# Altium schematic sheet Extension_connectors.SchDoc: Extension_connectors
size A4; Date: Not used; ApprovedBy: Not used; CheckedBy: Not used; Author: Not used; CompanyName: STMicroelectronics; DrawnBy: Not used; Engineer: Not used; Organization: Not used; Address1: Not used; Address2: Not used; Address3: Not used; Address4: Not used; DocumentNumber: Not used; Revision: Not used; SheetNumber: 8; SheetTotal: 12
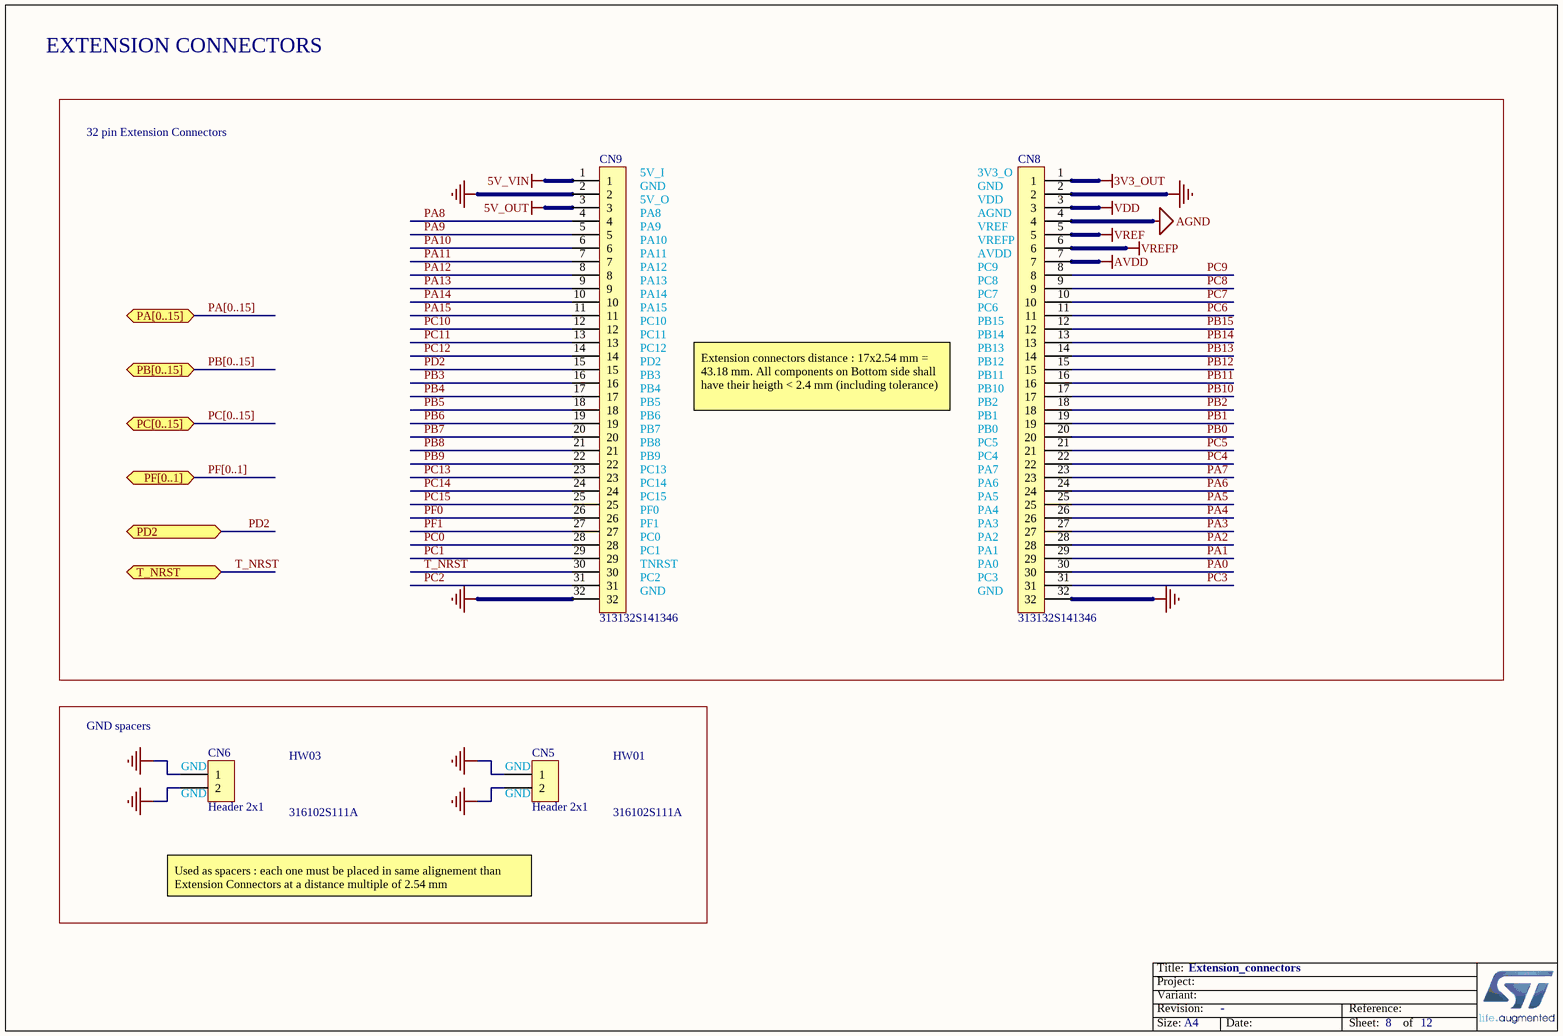
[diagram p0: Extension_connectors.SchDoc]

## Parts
CN5  Header 2x1  [CON_LYCONN_313102S141346]
CN6  Header 2x1  [CON_LYCONN_313102S141346]
CN8  value 313132S141346  [CON_LYCONN_313132S141346]  (hidden comment: Header 32x1)
CN9  value 313132S141346  [CON_LYCONN_313132S141346]  (hidden comment: Header 32x1)
HW01  value 316102S111A  (hidden comment: JUMPER_OPEN)
HW03  value 316102S111A  (hidden comment: JUMPER_OPEN)

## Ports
PA[0..15] (bidir), PB[0..15] (bidir), PC[0..15] (bidir), PD2, PF[0..1] (bidir), T_NRST

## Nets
3V3_OUT: CN8.1
5V_OUT: CN9.3
5V_VIN: CN9.1
AGND: CN8.4
AVDD: CN8.7
GND: CN5.1 CN5.2 CN6.1 CN6.2 CN8.2 CN8.32 CN9.2 CN9.32
VDD: CN8.3
VREF: CN8.5
VREFP: CN8.6
PA0: CN8.30
PA1: CN8.29
PA2: CN8.28
PA3: CN8.27
PA4: CN8.26
PA5: CN8.25
PA6: CN8.24
PA7: CN8.23
PA8: CN9.4
PA9: CN9.5
PA10: CN9.6
PA11: CN9.7
PA12: CN9.8
PA13: CN9.9
PA14: CN9.10
PA15: CN9.11
PB0: CN8.20
PB1: CN8.19
PB2: CN8.18
PB3: CN9.16
PB4: CN9.17
PB5: CN9.18
PB6: CN9.19
PB7: CN9.20
PB8: CN9.21
PB9: CN9.22
PB10: CN8.17
PB11: CN8.16
PB12: CN8.15
PB13: CN8.14
PB14: CN8.13
PB15: CN8.12
PC0: CN9.28
PC1: CN9.29
PC2: CN9.31
PC3: CN8.31
PC4: CN8.22
PC5: CN8.21
PC6: CN8.11
PC7: CN8.10
PC8: CN8.9
PC9: CN8.8
PC10: CN9.12
PC11: CN9.13
PC12: CN9.14
PC13: CN9.23
PC14: CN9.24
PC15: CN9.25
PD2: CN9.15 ; port PD2
PF0: CN9.26
PF1: CN9.27
T_NRST: CN9.30 ; port T_NRST

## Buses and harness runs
bus PA[0..15] = port PA[0..15]
bus PB[0..15] = port PB[0..15]
bus PC[0..15] = port PC[0..15]
bus PF[0..1] = port PF[0..1]

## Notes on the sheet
- EXTENSION CONNECTORS
- 32 pin Extension Connectors
- (near CN9) 5V_I
- (near CN8) 3V3_O
- (near CN9) GND
- (near CN9) 5V_O
- (near CN9) PA8
- (near CN9) PA10
- (near CN9) PA9
- (near CN8) GND
- (near CN8) VDD
- (near CN8) VREF
- (near CN8) AGND
- (near CN8) VREFP
- (near CN9) PA15
- (near CN9) PA14
- (near CN9) PA13
- (near CN9) PA12
- (near CN9) PA11
- (near CN8) AVDD
- (near CN8) PC6
- (near CN8) PC7
- (near CN8) PC8
- (near CN8) PC9
- (near CN9) PB3
- (near CN9) PD2
- (near CN9) PC12
- (near CN9) PC11
- (near CN9) PC10
- (near CN8) PB11
- (near CN8) PB12
- (near CN8) PB13
- (near CN8) PB14
- (near CN8) PB15
- (near CN9) PB7
- (near CN9) PB8
- (near CN9) PB6
- (near CN9) PB5
- (near CN9) PB4
- Extension connectors distance : 17x2.54 mm = 43.18 mm. All components on Bottom side shall have their heigth < 2.4 mm (including tolerance)
- (near CN8) PC5
- (near CN8) PB0
- (near CN8) PB1
- (near CN8) PB2
- (near CN8) PB10
- (near CN9) PF0
- (near CN9) PC15
- (near CN9) PC14
- (near CN9) PC13
- (near CN9) PB9
- (near CN8) PA4
- (near CN8) PA5
- (near CN8) PA6
- (near CN8) PA7
- (near CN8) PC4
- (near CN9) TNRST
- (near CN9) PC2
- (near CN9) PC1
- (near CN9) PC0
- (near CN9) PF1
- (near CN8) PC3
- (near CN8) PA0
- (near CN8) PA1
- (near CN8) PA2
- (near CN8) PA3
- GND spacers
- (near CN6) GND
- (near CN5) GND
- Used as spacers : each one must be placed in same alignement than Extension Connectors at a distance multiple of 2.54 mm

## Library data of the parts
CN5 CN6 = MCD-01668: Header 2x1, 2.54mm, VR, TH, height 5.84mm/5.08 mm, height total 13.46 mm; Part_Type: Connector; Manufacturer_Part_Number: 313102S141346; Manufacturer: LYCONN; Provided_By: SUBCO
CN8 CN9 = MCD-01728: 'Header 32x1, 2.54mm, VR, TH, height 5.84mm/5.08 mm, height total 13.46 mm; Part_Type: Connector; Manufacturer: LYCONN
HW01 HW03 = MCD-01849: Jumper, height 6mm, Black, 2.54mm, 3A, 20 mohm, open; Part_Type: Mechanical; Manufacturer: JIUBABA; Provided_By: SUBCO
